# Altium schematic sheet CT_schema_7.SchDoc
size 147 x 119 mm
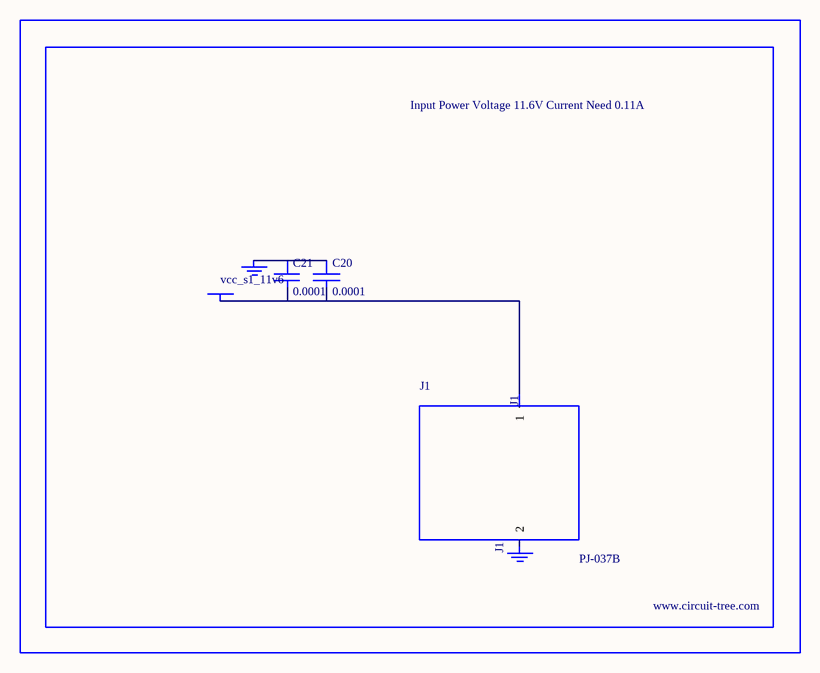
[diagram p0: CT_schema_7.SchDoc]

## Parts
BORDER6  (no value)
C20  0.0001  [EXV-9H]
C21  0.0001  [EXV-9H]
GND_INSTANCE_6_0  (no value)
GND_INSTANCE_6_1  (no value)
J1  PJ-037B  [PJ-037B_PACKAGE]
POWER_INSTANCE_6_0  vcc_s1_11v6

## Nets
NetC20_1: C20.1 C21.1 GND_INSTANCE_6_0.0(GND)
NetC20_2: C20.2 C21.2 J1.1 POWER_INSTANCE_6_0.0(PWR)

Not connected (* = marked no-connect by the designer): GND_INSTANCE_6_1 0(GND); J1 2

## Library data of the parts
BORDER6 = BORDER_PAGE6
C20 C21 = EDK107M035A9HAA
GND_INSTANCE_6_0 GND_INSTANCE_6_1 = GND
POWER_INSTANCE_6_0 = PWR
